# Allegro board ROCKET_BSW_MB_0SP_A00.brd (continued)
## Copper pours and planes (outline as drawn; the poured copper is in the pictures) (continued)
SLEEVE on BOTTOM: 148.18,85.93 147.95,86.15 147.95,87.74 148.11,87.89 148.7,87.89 149.07,87.52 149.07,87.31 149.31,87.06 149.31,86.12 149.12,85.93
SLEEVE on BOTTOM: 144.96,89.76 144.91,89.81 144.07,89.81 144.01,89.87 143.03,89.87 143.03,89.87 143.03,90.05 143.06,90.09 144.26,90.09 144.7,90.53 145.09,90.53 145.31,90.3 145.31,89.96 145.12,89.76
SLEEVE on L3: 144.6,90.55 145.46,90.55 145.8,90.89 145.8,92.59 146.62,93.41 148.72,93.41 148.91,93.22 148.91,92.89 148.71,92.68 146.99,92.68 146.57,92.27 146.57,90.56 145.79,89.78 144.6,89.78 144.4,89.98 144.4,90.34
SLEEVE_R on TOP: 150.97,94.81 150.97,95.66 151.07,95.76 153.55,95.76 153.67,95.63 153.67,94.47 153.54,94.34 151.44,94.34
SLEEVE_R on BOTTOM: 152.02,95.12 152.1,95.2 153.84,95.2 153.84,93.9 153.82,93.88 152.98,93.88 152.73,94.13 152.12,94.13 152.02,94.24
TP_VDD_1D8V on BOTTOM: 60.66,66.08 60.58,66.16 60.58,66.91 61.37,67.7 62.07,67.7 62.63,67.14 62.63,66.95 61.76,66.08
VREF_CA on TOP: 125.58,33.31 125.14,33.75 125.14,34.11 125.8,34.77 126.47,34.77 126.58,34.66 126.58,33.4 126.49,33.31 ; 1 cut-out
VREF_CA_R1207 on TOP: 126.81,34.17 126.77,34.21 126.77,35.01 126.82,35.05 128.31,35.05 128.89,35.63 129.18,35.63 129.39,35.41 129.39,34.22 129.34,34.17 ; 4 cut-outs

Small or netless copper shapes (teardrops, artwork), in the pictures only: 3 on TOP, 7 on BOTTOM

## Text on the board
Ref Des/Silkscreen Bottom: X1802:32.768KHZ | F5501:1.1A/24V | F5701:1.1A/6V | X1601:19.2MHZ | F5502:1.1A/6V | MADE IN TAIWAN | CNJV4 | 15235-SC | ROCKET MB 0SP
User.Comments: ALYNE2
Ref Des/Silkscreen Top: CNJV4
User.27: ByImpedance:100.0@_REF_L1=("3.5/10.0(L1)")|_REF_L6=("3.5/10.0(L6)")|Type="DP"|_REF_L4=("4.0/9.0(L4)" "3.5/7.0(L4)")|_REF_L3=("4.0/9.0(L3)" "3.5/7.0(L3)")|imp="100.0" | ByImpedance:37.5@_REF_L1=("7.0(L1)")|_REF_L6=("7.0(L6)")|Type="SE"|_REF_L4=("9.0(L4)")|_REF_L3=("9.0(L3)")|imp="37.5" | ByImpedance:40.0@_REF_L1=("6.5(L1)")|_REF_L6=("6.5(L6)")|Type="SE"|_REF_L4=("8.0(L4)")|_REF_L3=("8.0(L3)")|imp="40.0" | ByImpedance:45.0@_REF_L1=("5.0(L1)")|_REF_L6=("5.0(L6)")|Type="SE"|_REF_L4=("6.5(L4)")|_REF_L3=("6.5(L3)")|imp="45.0" | ByImpedance:47.0@_REF_L1=("4.5(L1)")|_REF_L6=("4.5(L6)")|Type="SE"|_REF_L4=("6.0(L4)")|_REF_L3=("6.0(L3)")|imp="47.0" | ByImpedance:48.0@_REF_L1=("4.5(L1)")|_REF_L6=("4.5(L6)")|Type="SE"|_REF_L4=("5.5(L4)")|_REF_L3=("5.5(L3)")|imp="48.0" | ByImpedance:50.0@_REF_L1=("4.0(L1)")|_REF_L6=("4.0(L6)")|Type="SE"|_REF_L4=("5.0(L4)")|_REF_L3=("5.0(L3)")|imp="50.0" | ByImpedance:52.0@_REF_L1=("3.5(L1)")|_REF_L6=("3.5(L6)")|Type="SE"|_REF_L4=("4.5(L4)")|_REF_L3=("4.5(L3)")|imp="52.0" | ByImpedance:72.0@_REF_L1=("5.5/4.0(L1)")|_REF_L6=("5.5/4.0(L6)")|Type="DP"|_REF_L4=("6.5/4.0(L4)")|_REF_L3=("6.5/4.0(L3)")|imp="72.0" | ByImpedance:76.0@_REF_L1=("5.0/4.0(L1)")|_REF_L6=("5.0/4.0(L6)")|Type="DP"|_REF_L4=("5.5/4.0(L4)")|_REF_L3=("5.5/4.0(L3)")|imp="76.0" | ByImpedance:80.0@_REF_L1=("4.5/4.0(L1)")|_REF_L6=("4.5/4.0(L6)")|Type="DP"|_REF_L4=("6.0/6.0(L4)")|_REF_L3=("6.0/6.0(L3)")|imp="80.0" | ByImpedance:85.0@_REF_L1=("4.0/4.5(L1)")|_REF_L6=("4.0/4.5(L6)")|Type="DP"|_REF_L4=("5.0/5.5(L4)" "4.5/4.5(L4)")|_REF_L3=("5.0/5.5(L3)" "4.5/4.5(L3)")|imp="85.0" | ByImpedance:88.0@_REF_L1=("3.5/4.5(L1)")|_REF_L6=("3.5/4.5(L6)")|Type="DP"|_REF_L4=("4.0/4.5(L4)" "3.5/4.0(L4)")|_REF_L3=("4.0/4.5(L3)" "3.5/4.0(L3)")|imp="88.0" | ByImpedance:90.0@_REF_L1=("4.0/6.0(L1)")|_REF_L6=("4.0/6.0(L6)")|Type="DP"|_REF_L4=("5.0/8.0(L4)" "4.0/5.0(L4)")|_REF_L3=("5.0/8.0(L3)" "4.0/5.0(L3)")|imp="90.0" | LayerIndex:nil | Source:6-1.0-7c.xls | artWorks:("_REF_L3" "_REF_L4" "_REF_L6" "_REF_L1") | gtImpOutlineUsed:BOARD GEOMETRY/PANEL_OUTLINE
User.28: +DC_IN | GND | 1V_CPU_CORE | GFX_CORE | AUD_AGND | 3D3V_S5 | 5V_S0
User.31: Board Accuracy Check,Oct 19 11:37:45 2015,Passed | Component Overlap Check,Jul 27 15:55:41 2015,57 errors | Dummy-Static-No Shape On Layer Check,Oct 19 11:37:45 2015,Passed | Split Plane Check,Jul 23 04:07:54 2015,Passed
User.32: F5501:1.1A/24V | F5502:1.1A/6V | F5701:1.1A/6V | X1601:19.2MHZ | X1802:32.768KHZ | MADE IN TAIWAN | ROCKET MB
User.35: This gerber is just for your reference to find the DP impedance traces in layer L1. | DP IMPEDANCE TABLE: L1 | * - Denotes that this Impedance | is NOT used | IMP(Ohm) | *72.0 | 76.0 | *80.0 | 85.0 | 88.0 | *90.0 | *100.0 | WIDTH(mils) | 5.5/4.0 | 5.0/4.0 | 4.5/4.0 | 4.0/4.5 | 3.5/4.5 | 4.0/6.0 | 3.5/10.0 | TYPE | DP
User.37: This gerber is just for your reference to find the SE impedance traces in layer L1. | SE IMPEDANCE TABLE: L1 | * - Denotes that this Impedance | is NOT used | IMP(Ohm) | *37.5 | *40.0 | *45.0 | 47.0 | *48.0 | 50.0 | 52.0 | WIDTH(mils) | 7.0 | 6.5 | 5.0 | 4.5 | 4.0 | 3.5 | TYPE | SE
User.39: This gerber is just for your reference to find the DP impedance traces in layer L3. | DP IMPEDANCE TABLE: L3 | * - Denotes that this Impedance | is NOT used | IMP(Ohm) | *72.0 | 76.0 | *80.0 | *85.0 | 85.0 | 88.0 | *88.0 | *90.0 | *100.0 | WIDTH(mils) | 6.5/4.0 | 5.5/4.0 | 6.0/6.0 | 5.0/5.5 | 4.5/4.5 | 4.0/4.5 | 3.5/4.0 | 5.0/8.0 | 4.0/5.0 | 4.0/9.0 | 3.5/7.0 | TYPE | DP
User.41: This gerber is just for your reference to find the SE impedance traces in layer L3. | SE IMPEDANCE TABLE: L3 | * - Denotes that this Impedance | is NOT used | IMP(Ohm) | *37.5 | *40.0 | *45.0 | 47.0 | *48.0 | 50.0 | 52.0 | WIDTH(mils) | 9.0 | 8.0 | 6.5 | 6.0 | 5.5 | 5.0 | 4.5 | TYPE | SE
User.43: This gerber is just for your reference to find the DP impedance traces in layer L4. | DP IMPEDANCE TABLE: L4 | * - Denotes that this Impedance | is NOT used | IMP(Ohm) | *72.0 | 76.0 | *80.0 | *85.0 | 85.0 | 88.0 | *88.0 | *90.0 | *100.0 | WIDTH(mils) | 6.5/4.0 | 5.5/4.0 | 6.0/6.0 | 5.0/5.5 | 4.5/4.5 | 4.0/4.5 | 3.5/4.0 | 5.0/8.0 | 4.0/5.0 | 4.0/9.0 | 3.5/7.0 | TYPE | DP
User.45: Note:Refer to DRILL layer for ELLIPSE drill direction | FIGURE | SIZE | 10.0 | 16.0 | 20.0 | 28.0 | 117.0 | 142.0 | 197.0 | 237.0 | 46.0 | 65.0 | 86.0 | 119.0 | 158.0 | 36.0x18.0 | 63.0x36.0 | 71.0x32.0 | 79.0x32.0 | 93.0x36.0 | DRILL CHART: TOP to BOTTOM | ALL UNITS ARE IN MILS | PLATED | NON-PLATED | QTY | 2300 | 568 | 19 | 9 | 4 | 1 | 2 | 3 | This gerber is just for your reference to find the DP impedance traces in layer L6. | This gerber is just for your reference to find the SE impedance traces in layer L4. | This gerber is just for your reference to find the SE impedance traces in layer L6. | DP IMPEDANCE TABLE: L6 | SE IMPEDANCE TABLE: L4 | SE IMPEDANCE TABLE: L6 | * - Denotes that this Impedance | is NOT used | ROCKET MB 0SP | Model | PCB_NO | 15235 | VER. | SC | Layer | DRILL | L1 | L2GND | L3 | TMASK | TPLACE | TSILK | TSMD | Designer | Rebecca | Date | 10/19/2015 | IMP(Ohm) | *37.5 | *72.0 | *40.0 | 76.0 | *45.0 | *80.0 | 47.0 | 85.0 | *48.0 | 88.0 | *90.0 | 50.0 | *100.0 | 52.0 | WIDTH(mils) | 7.0 | 9.0 | 6.5 | 8.0 | 5.0 | 4.5 | 6.0 | 5.5 | 4.0 | 3.5 | 5.5/4.0 | 5.0/4.0 | 4.5/4.0 | 4.0/4.5 | 3.5/4.5 | 4.0/6.0 | 3.5/10.0 | TYPE | SE | DP | BMASK | BPLACE | BSILK | BSMD | L4 | L5VCC | L6
